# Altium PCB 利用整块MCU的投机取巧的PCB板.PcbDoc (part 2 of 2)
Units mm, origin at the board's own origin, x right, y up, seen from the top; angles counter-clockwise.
Board outline 162.08 x 191.08 mm, 2 copper layers (Top Layer, Bottom Layer); 156 components, 178 nets, 550 pads, 92 vias.
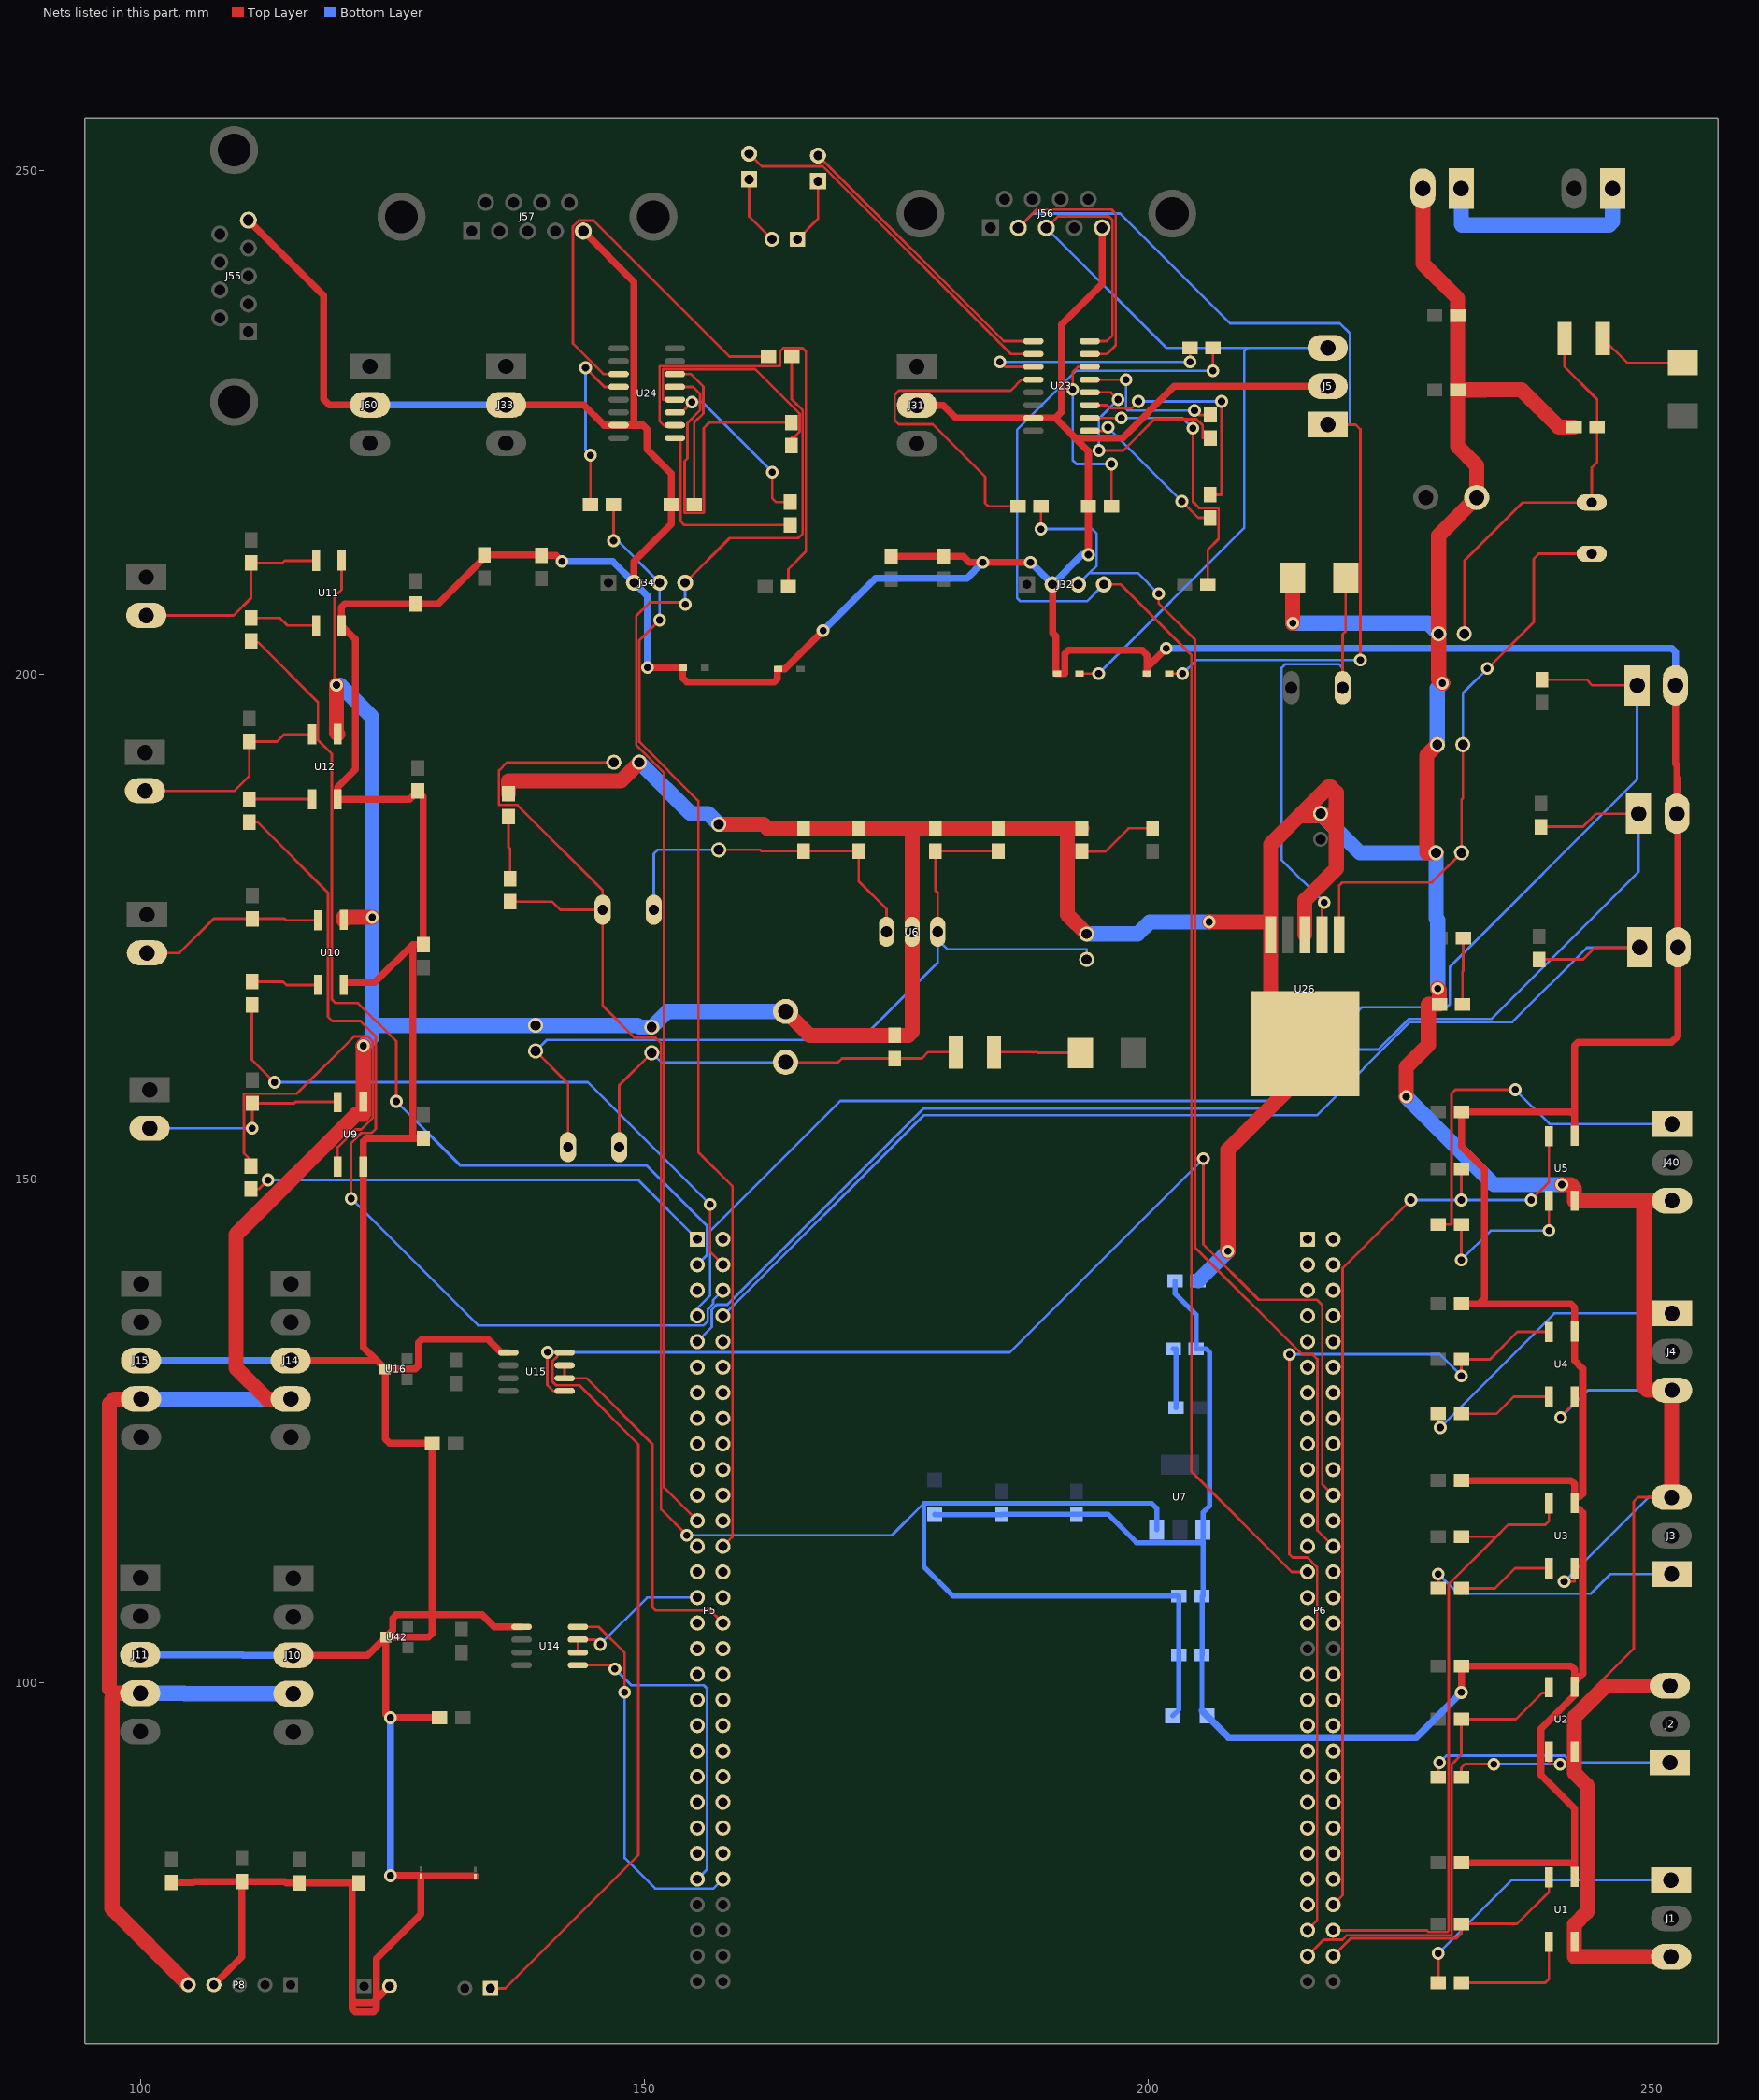
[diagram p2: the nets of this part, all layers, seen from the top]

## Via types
v1: diameter 1.27, hole 0.711, Top Layer to Bottom Layer, 92 vias

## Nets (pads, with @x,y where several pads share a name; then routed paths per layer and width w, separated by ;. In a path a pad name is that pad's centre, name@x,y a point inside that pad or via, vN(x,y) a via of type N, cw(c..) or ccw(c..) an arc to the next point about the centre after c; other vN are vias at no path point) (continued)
GND: C8.2 C12.2 C13.2 C17.2 C30.2 C33.2 C37.2 C45.2 C46.2 C48.2 C52.2 C73.2 C74.2 C75.2 C76.2 C77.2 C78.2 C80.2 C81.2 D9.1 J1.3 J2.3 J3.3 J4.3 J10.4 J11.4 J14.4 J15.4 J40.3 LED1.2 LED3.2 LED6.2 P2.2 P8.5 R24.1 U1.2 U2.2 U3.2 U4.2 U5.2 U6.2 U9.3 U10.3 U11.3 U12.3 U26.3 U26.5 | length 786.2
  Top Layer w0.254: U12.3@119.589,194.108 119.589,199.339 119.278,199.65 119.278,207.747 119.97,208.438 U11.3@119.97,211.335 ; v1(240.919,126.289) 240.919,126.371 242.31,127.762 U4.2@242.31,128.354 ; v1(241.275,110.001) 242.31,110.033 U3.2@242.31,111.336 ; U2.2@242.31,93.125 242.31,96.565 242.31,97.472 248.183,103.346 248.183,117.96 248.602,118.379 J3.3@251.938,118.379
  Top Layer w0.5: U26.3@215.556,160.494 U26.3@215.556,163.377
  Top Layer w1.5: J11.4@99.999,98.938 97.693,98.938 ; J15.4@100.065,128.135 97.426,128.135 96.926,127.635 96.926,99.377 97.366,98.938 97.693,98.938 ; P8.5@104.751,70.009 97.18,77.58 97.18,98.425 97.693,98.938 ; J14.4@114.924,128.135 112.568,128.135 109.495,131.208 109.495,144.445 121.437,156.388 122.104,156.388 122.129,156.413 U9.3@122.129,157.626 v1(122.129,163.17) ; v1(119.456,198.97) 119.456,194.241 U12.3@119.589,194.108 ; U10.3@120.173,175.66 120.173,175.899 120.203,175.929 v1(122.996,175.929) ; LED1.2@136.529,188.193 136.529,189.433 136.554,189.459 147.674,189.459 C52.2@149.524,191.308 ; C48.2@157.396,185.162 161.828,185.162 162.226,184.763 C46.2@165.82,184.763 C45.2@171.281,184.763 177.165,184.763 ; C12.2@164.034,166.584 166.411,164.207 C8.2@174.838,164.207 176.213,164.207 176.575,164.569 U6.2@176.575,174.484 176.575,184.174 177.165,184.763 ; LED6.2@193.415,184.756 192.405,184.756 ; C30.2@193.898,174.277 191.973,176.202 191.973,184.325 192.405,184.756 ; v1(206.07,175.463) U26.5@212.156,175.463 ; v1(207.92,142.802) 207.92,152.859 U26.3@215.556,160.494 ; U26.5@212.156,174.202 U26.5@212.156,175.463 ; v1(214.347,205.121) D9.1@214.347,209.645 ; U26.3@215.556,163.377 212.166,163.377 212.166,183.159 215.022,186.015 ; U26.3@215.556,174.202 215.556,177.622 ; C81.2@217.108,186.221 C81.2@217.314,186.015 ; v1(225.603,158.115) 225.603,161.061 227.813,163.271 227.813,167.267 227.838,167.292 LED3.2@228.903,167.292 228.903,168.681 v1(228.727,168.857) ; P2.2@227.259,248.236 227.259,240.796 230.717,237.338 C77.2@230.717,235.626 C75.2@230.717,228.26 ; C80.2@228.559,182.332 227.66,182.332 227.635,182.357 227.635,192.002 C76.2@228.693,193.06 ; v1(229.21,199.161) 228.827,199.544 C74.2@228.827,204.056 228.827,213.814 C78.2@232.599,217.586 232.599,220.766 230.717,222.648 C75.2@230.717,228.26 ; v1(241.046,149.403) 241.935,149.403 242.31,149.028 U5.2@242.31,147.803 ; C73.2@242.263,224.584 240.741,224.584 237.056,228.27 233.477,228.27 233.467,228.26 C75.2@230.717,228.26 ; U5.2@242.31,147.785 U5.2@242.31,147.803 ; J2.3@251.771,99.665 245.41,99.665 242.31,96.565 U2.2@242.31,93.125 242.31,91.014 243.535,89.789 243.535,77.222 242.31,75.997 U1.2@242.31,74.252 242.31,72.814 242.341,72.782 J1.3@251.881,72.782 ; J3.3@251.938,118.379 J4.3@251.938,129.002 ; J4.3@251.984,129.002 J4.3@251.938,129.002 ; J40.3@251.984,147.798 249.555,147.798 ; 177.165,184.763 C37.2@178.883,184.763 C33.2@185.124,184.763 190.671,184.763 190.678,184.756 192.405,184.756 ; U26.5@212.156,175.463 212.156,183.159 215.011,186.015 215.022,186.015 ; 215.022,186.015 217.856,188.849 218.123,188.849 218.669,188.303 218.669,185.469 ; 215.022,186.015 C81.2@217.314,186.015 ; 215.556,177.622 215.556,177.633 218.669,180.746 ; 215.556,177.622 218.669,180.735 218.669,180.746 ; C81.2@217.314,186.015 218.669,184.66 ; C81.2@217.314,186.015 218.123,186.015 218.669,185.469 ; 218.669,180.746 218.669,184.66 ; 218.669,184.66 218.669,185.469 ; U5.2@242.31,147.803 243.561,147.803 243.566,147.798 249.555,147.798 ; 249.555,147.798 249.174,147.417 249.174,129.383 249.555,129.002 J4.3@251.938,129.002
  Bottom Layer w0.254: v1(240.919,126.289) 243.632,129.002 J4.3@251.984,129.002 ; v1(241.275,110.001) 249.652,118.379 J3.3@251.938,118.379
  Bottom Layer w1.5: J11.4@99.999,98.938 104.369,98.938 104.418,98.888 J10.4@115.192,98.888 ; J15.4@100.065,128.135 J14.4@114.924,128.135 ; v1(119.456,198.97) 119.798,198.97 122.996,195.771 v1(122.996,175.929) 122.996,165.129 ; v1(122.129,163.17) 122.996,164.037 122.996,165.129 ; C52.2@149.524,191.308 154.612,186.22 156.337,186.22 C48.2@157.396,185.162 ; C12.2@164.034,166.584 152.304,166.584 C13.2@150.743,165.023 149.503,165.023 149.328,165.199 C17.2@139.218,165.199 123.066,165.199 122.996,165.129 ; C30.2@193.898,174.277 198.966,174.277 200.152,175.463 v1(206.07,175.463) ; R24.1@204.964,139.846 v1(207.92,142.802) ; v1(214.347,205.121) 227.762,205.121 C74.2@228.827,204.056 ; C81.2@217.108,186.221 220.997,182.332 C80.2@228.559,182.332 228.559,175.809 228.727,175.641 v1(228.727,168.857) ; v1(225.603,158.115) 234.315,149.403 v1(241.046,149.403) ; C76.2@228.693,193.06 228.693,198.645 v1(229.21,199.161)
GND-SYS: C1.2 C3.2 C7.2 C10.2 C11.2 C14.2 C19.1 C20.1 C21.1 C22.1 C24.1 C31.1 C32.2 C34.1 C35.1 C38.2 C43.2 C47.1 C49.2 C53.2 C55.2 C61.2 C65.2 C67.2 C69.2 C71.1 C72.1 C90.1 C91.1 D40.1 D41.1 D42.1 D43.1 J5.2 J10.3 J11.3 J12.2 J13.2 J14.3 J15.3 J16.2 J31.2 J32.2 J33.2 J34.2 J55.5 J56.5 J57.5 J60.2 LED2.2 P8.4 P9.2 R24.2 U1.3 U2.3 U3.3 U4.3 U5.3 U7.1 U9.2 U10.2 U11.2 U12.2 U14.5 U15.5 U16.3 U23.15 U24.15 U42.3 | length 985.6
  Top Layer w0.7: C14.2@103.072,80.149 105.258,80.149 105.361,80.252 C11.2@110.072,80.252 ; P8.4@107.291,70.009 110.072,72.79 C11.2@110.072,80.252 ; J55.5@110.728,245.101 118.186,237.642 118.186,227.33 118.727,226.789 J60.2@122.799,226.789 ; J14.3@114.924,131.945 123.469,131.945 ; J10.3@115.192,102.698 122.566,102.698 U42.3@124.369,104.501 ; U10.2@120.173,169.209 120.173,169.443 123.247,169.443 127.025,173.222 127.025,173.197 ; P9.2@124.733,69.866 123.444,68.577 ; v1(124.816,80.823) 127.852,80.823 C3.2@127.852,80.797 ; C31.1@128.08,153.997 127.051,153.997 ; C90.1@129.703,96.5 v1(124.816,96.5) 124.696,96.5 124.369,96.827 U42.3@124.369,104.501 ; C1.2@133.237,80.76 133.237,80.797 C3.2@127.852,80.797 ; J33.2@136.287,226.789 143.993,226.789 146.025,224.757 U24.15@147.463,224.757 148.646,224.757 ; U15.5@136.512,132.732 135.788,132.732 134.459,134.061 127.953,134.061 127.61,133.718 127.61,131.445 127.279,131.115 U16.3@124.299,131.115 ; U14.5@137.831,105.517 135.122,105.517 133.921,106.718 128.971,106.718 ; v1(141.834,211.252) 141.251,211.835 C61.2@139.803,211.835 139.803,211.88 C72.1@134.126,211.88 134.126,211.605 129.54,207.019 C35.1@127.336,207.019 120.297,207.019 119.97,206.692 U11.2@119.97,204.883 121.336,203.517 121.336,197.523 121.336,190.596 119.589,188.849 U12.2@119.589,187.656 126.733,187.656 C47.1@127.539,188.462 128.08,187.921 C34.1@128.08,173.222 127.051,173.222 127.025,173.197 ; J57.5@143.96,244.019 148.996,238.982 148.996,225.107 148.646,224.757 ; J34.2@148.985,209.134 148.985,211.252 152.668,214.935 C67.2@152.668,216.881 152.668,219.95 150.266,222.352 150.266,224.351 149.86,224.757 148.646,224.757 ; v1(150.317,200.699) D43.1@153.797,200.699 ; D43.1@153.807,200.699 D43.1@153.797,200.699 ; v1(167.742,204.368) 163.945,200.572 D42.1@163.299,200.572 163.195,200.572 163.195,199.581 162.877,199.263 154.242,199.263 153.797,199.707 D43.1@153.797,200.699 ; J31.2@177.054,226.745 179.655,226.745 180.925,225.475 U23.15@188.611,225.475 190.78,225.475 ; v1(188.327,211.15) v1(183.591,211.15) 182.267,211.15 181.661,211.757 C69.2@179.719,211.757 ; J32.2@190.514,208.963 190.514,204.151 190.856,203.81 190.856,200.108 D41.1@190.952,200.108 191.694,200.108 191.719,200.133 191.719,202.044 192.088,202.413 199.415,202.413 199.898,201.93 D40.1@199.898,200.108 ; v1(194.07,211.912) C65.2@194.07,216.71 194.07,222.185 190.78,225.475 ; J56.5@195.435,244.341 195.435,238.768 191.414,234.747 191.414,226.06 190.817,225.463 ; D40.1@199.875,200.108 D40.1@199.898,200.108 ; v1(201.803,202.616) 199.974,200.787 199.974,200.108 D40.1@199.898,200.108 ; J5.2@217.817,228.622 202.587,228.622 197.46,223.495 192.786,223.495 190.817,225.463 ; C19.1@231.078,82.117 241.935,82.117 242.31,81.742 ; v1(231.078,99.009) C20.1@231.078,101.634 241.959,101.634 242.31,101.282 U2.3@242.31,100.051 ; C21.1@231.078,120.049 241.959,120.049 242.31,119.697 U3.3@242.31,118.389 ; C22.1@231.078,137.575 232.812,137.575 ; U1.3@242.31,80.704 242.31,81.742 ; U5.3@242.31,154.237 242.31,156.267 ; J13.2@252.33,198.944 252.33,191.154 252.472,191.012 252.472,189.738 ; J16.2@252.472,186.209 252.472,189.738 ; C11.2@110.072,80.252 114.351,80.252 114.478,80.125 C10.2@115.787,80.125 115.787,80.112 C7.2@121.031,80.112 ; 121.031,68.58 C7.2@121.031,80.01 ; 121.031,68.58 121.031,67.627 121.349,67.31 123.126,67.31 123.444,67.627 123.444,68.577 ; 121.031,68.58 121.361,68.25 123.117,68.25 123.444,68.577 ; C7.2@121.031,80.01 121.655,80.01 C7.2@121.655,80.125 121.031,80.125 C7.2@121.031,80.112 ; C7.2@121.031,80.01 C7.2@121.031,80.112 ; 123.444,68.577 123.444,72.593 127.852,77.001 C3.2@127.852,80.791 C3.2@127.852,80.797 ; 123.469,131.945 U16.3@124.299,131.115 ; 123.469,131.945 122.149,133.265 122.149,148.107 122.129,148.127 U9.2@122.129,151.175 122.129,153.67 122.456,153.997 127.051,153.997 ; U16.3@124.299,131.115 124.299,124.142 124.708,123.733 C91.1@128.971,123.733 128.971,106.718 ; U42.3@124.369,104.501 128.588,104.501 128.971,104.884 128.971,106.718 ; U42.3@124.369,104.501 125.044,105.177 125.044,106.362 125.4,106.718 128.971,106.718 ; 127.025,173.197 127.025,154.022 127.051,153.997 ; C69.2@179.719,211.757 C71.1@174.512,211.757 174.512,211.76 179.719,211.76 C69.2@179.719,211.757 ; 190.78,225.475 190.806,225.475 190.817,225.463 ; 232.812,137.575 241.935,137.575 242.31,137.2 U4.3@242.31,134.806 242.31,131.953 243.129,131.134 243.129,118.745 242.773,118.389 U3.3@242.31,118.389 ; 232.812,137.575 233.35,138.112 233.35,150.915 231.078,153.187 C24.1@231.078,156.625 241.952,156.625 242.31,156.267 ; 242.31,81.742 242.31,87.484 238.963,90.83 238.963,95.402 242.31,98.749 U2.3@242.31,99.576 U2.3@242.31,100.051 ; U2.3@242.31,100.051 243.129,100.87 243.129,116.84 242.773,117.196 242.31,117.196 U3.3@242.31,117.788 U3.3@242.31,118.389 ; 242.31,156.267 242.31,163.195 242.627,163.512 251.938,163.512 252.573,164.147 J12.2@252.573,172.947 252.573,189.738 252.548,189.763 252.497,189.763 252.472,189.738
  Bottom Layer w0.5: C55.2@178.824,116.68 178.842,116.662 185.485,116.662 C53.2@185.485,116.688 ; C53.2@185.485,116.694 C53.2@185.485,116.688 ; R24.2@202.678,139.846 202.678,138.569 204.772,136.474 LED2.2@204.772,133.117 205.74,133.117 206.121,132.736 206.121,117.54 205.447,116.865 U7.1@205.447,115.176 205.447,113.894 ; C43.2@205.342,108.588 C43.2@205.359,108.588 ; C32.2@205.855,96.68 205.342,97.193 C38.2@205.342,102.746 205.359,102.746 C43.2@205.359,108.588 ; C53.2@185.485,116.688 192.895,116.688 C49.2@192.895,116.694 196.012,116.694 198.838,113.868 205.421,113.868 205.447,113.894 ; C43.2@205.359,108.588 205.461,108.588 205.461,113.908 205.447,113.894
  Bottom Layer w0.7: J11.3@99.999,102.748 110.18,102.748 110.23,102.698 J10.3@115.192,102.698 ; J15.3@100.065,131.945 100.787,131.945 100.795,131.953 114.19,131.953 114.198,131.945 J14.3@114.924,131.945 ; J60.2@122.799,226.789 J33.2@136.287,226.789 ; v1(124.816,80.823) v1(124.816,96.5) ; v1(141.834,211.252) 146.867,211.252 J34.2@148.985,209.134 150.317,207.802 v1(150.317,200.699) ; v1(167.742,204.368) 172.949,209.575 182.016,209.575 v1(183.591,211.15) ; v1(188.327,211.15) J32.2@190.514,208.963 193.464,211.912 v1(194.07,211.912) ; v1(201.803,202.616) 251.961,202.616 252.33,202.248 J13.2@252.33,198.944 ; C32.2@205.342,97.193 205.342,97.18 207.984,94.539 226.607,94.539 v1(231.078,99.009)
IN1: J1.1 R1.2 | length 29
  Top Layer w0.254: R1.2@228.792,70.197 v1(228.792,73.127)
  Bottom Layer w0.254: v1(228.792,73.127) 236.067,80.402 J1.1@251.881,80.402
IN1_1: P6.58 R7.1 U1.4 | length 26
  Top Layer w0.254: P6.58@218.359,72.869 220.106,74.616 230.586,74.616 231.078,75.108 R7.1@231.078,76.039 236.592,76.039 239.77,79.216 U1.4@239.77,80.679
IN2: J2.1 R2.2 | length 24.9
  Top Layer w0.254: R2.2@228.792,90.585 228.792,91.919 v1(228.917,92.045)
  Bottom Layer w0.254: v1(228.917,92.045) 229.604,92.731 241.322,92.731 242.008,92.045 J2.1@251.771,92.045
IN2_1: P6.57 R6.1 U2.4 | length 47.3
  Top Layer w0.254: P6.57@215.819,72.869 217.422,74.473 219.278,74.473 219.726,74.921 230.002,74.921 230.124,75.043 230.124,91.869 231.078,92.823 R6.1@231.078,96.363 236.494,96.363 239.09,98.958 239.77,98.958 U2.4@239.77,99.551
IN3: J3.1 R50.2 | length 26.2
  Top Layer w0.254: R50.2@228.792,109.338 v1(228.792,110.759)
  Bottom Layer w0.254: v1(228.792,110.759) 230.738,108.812 243.939,108.812 245.885,110.759 J3.1@251.938,110.759
IN3_1: P6.56 R5.1 U3.4 | length 63.7
  Top Layer w0.254: P6.56@218.359,75.409 227.664,75.409 227.847,75.226 229.697,75.226 229.819,75.348 229.819,109.753 234.526,114.461 ; R5.1@231.078,114.461 234.526,114.461 ; U3.4@239.77,117.763 239.77,116.021 239.395,115.646 235.712,115.646 234.526,114.461
IN4: J4.1 R40.2 | length 29.1
  Top Layer w0.254: R40.2@228.792,126.653 228.792,125.487 v1(228.981,125.298)
  Bottom Layer w0.254: v1(228.981,125.298) 240.304,136.622 J4.1@251.984,136.622
IN4_1: P6.55 R4.1 U4.4 | length 89
  Top Layer w0.254: v1(214.02,132.563) 214.02,112.712 214.338,112.395 215.811,112.395 216.764,111.442 216.764,76.354 P6.55@215.819,75.409 ; v1(231.078,130.429) R4.1@231.078,132.071 233.925,132.071 236.652,134.798 239.77,134.798 U4.4@239.77,134.781
  Bottom Layer w0.254: v1(214.02,132.563) 228.944,132.563 v1(231.078,130.429)
IN5: J40.1 R31.2 | length 37.7
  Top Layer w0.254: R31.2@228.792,145.449 230.073,145.449 230.099,145.474 230.099,158.433 230.492,158.826 v1(236.423,158.826)
  Bottom Layer w0.254: v1(236.423,158.826) 239.832,155.418 J40.1@251.984,155.418
IN5_1: P6.54 R3.1 U5.4 | length 95.2
  Top Layer w0.254: P6.54@218.359,77.949 219.304,78.894 219.304,141.122 v1(226.06,147.879) ; v1(231.078,147.879) R3.1@231.078,150.972 ; v1(237.998,147.879) 239.77,149.651 U5.4@239.77,154.212
  Bottom Layer w0.254: v1(226.06,147.879) v1(231.078,147.879) v1(237.998,147.879)
IN_24V: P2.1 P4.1 | length 22
  Bottom Layer w1.5: P2.1@231.069,248.236 231.069,244.686 231.124,244.631 245.745,244.631 246.079,244.965 P4.1@246.079,248.236
K1: J12.1 P5.8 R51.2 | length 116.6
  Top Layer w0.254: R51.2@238.799,171.744 243.154,171.744 244.358,172.947 J12.1@248.763,172.947
  Bottom Layer w0.254: P5.8@157.807,136.369 177.724,156.286 216.738,156.286 225.984,165.532 236.144,165.532 243.535,172.923 248.763,172.923 J12.1@248.763,172.947
K2: J13.1 P5.7 R52.2 | length 140.7
  Top Layer w0.254: R52.2@239.067,199.517 243.484,199.517 244.057,198.944 J13.1@248.52,198.944
  Bottom Layer w0.254: P5.7@155.267,136.369 155.267,137.124 156.54,138.397 156.54,144.805 169.443,157.709 211.887,157.709 221.183,167.005 229.629,167.005 229.946,167.322 229.946,171.037 248.52,189.611 J13.1@248.52,198.944
K3: J16.1 P5.9 R53.2 | length 129.7
  Top Layer w0.254: R53.2@238.976,184.913 243.154,184.913 244.45,186.209 J16.1@248.662,186.209
  Bottom Layer w0.254: P5.9@155.267,133.829 156.692,135.254 156.692,136.982 157.188,137.477 158.255,137.477 177.724,156.947 211.861,156.947 217.729,162.814 222.834,162.814 225.857,165.837 234.061,165.837 248.662,180.438 J16.1@248.662,186.209
L1: P5.1 R20.2 | length 47.1
  Top Layer w0.254: R20.2@110.971,148.965 111.779,148.965 v1(112.674,149.86)
  Bottom Layer w0.254: v1(112.674,149.86) 149.397,149.86 P5.1@155.267,143.989
L1_out: J6.2 R26.2 U9.4 | length 21.2
  Top Layer w0.254: v1(111.1,154.991) 111.123,155.014 R26.2@111.123,157.474 115.291,157.474 115.418,157.601 U9.4@119.589,157.601
  Bottom Layer w0.254: J6.2@100.92,154.993 111.098,154.993 v1(111.1,154.991)
L2: P5.4 R21.2 | length 63.4
  Top Layer w0.254: R21.2@111.08,167.253 111.08,161.792 v1(113.309,159.563) ; v1(156.54,147.422) 156.54,142.716 P5.4@157.807,141.449
  Bottom Layer w0.254: v1(113.309,159.563) 144.399,159.563 v1(156.54,147.422)
L2_out: J7.2 R27.2 U10.4 | length 18.4
  Top Layer w0.254: J7.2@100.666,172.392 103.896,172.392 107.29,175.785 R27.2@111.123,175.785 114.3,175.785 114.45,175.635 U10.4@117.633,175.635
L3: P5.3 R22.2 | length 93.6
  Top Layer w0.254: R22.2@111.004,203.336 111.004,203.2 111.709,203.2 117.627,197.282 117.627,193.523 118.999,192.151 118.999,167.792 119.38,167.411 121.615,167.411 125.4,163.627 v1(125.4,157.658)
  Bottom Layer w0.254: v1(125.4,157.658) 131.775,151.282 150.266,151.282 156.21,145.339 156.21,142.392 P5.3@155.267,141.449
L3_out: J8.2 R28.2 U11.4 | length 21.1
  Top Layer w0.254: J8.2@100.59,205.876 109.26,205.876 111.004,207.62 R28.2@111.004,211.083 114.097,211.083 114.323,211.309 U11.4@117.43,211.309
L4: P5.6 R25.2 | length 90.7
  Top Layer w0.254: R25.2@110.826,185.37 111.62,185.37 118.631,178.359 118.631,166.052 119.05,165.633 121.844,165.633 123.368,164.109 123.368,154.94 122.953,154.525 121.92,154.525 120.929,153.534 v1(120.929,148.006)
  Bottom Layer w0.254: v1(120.929,148.006) 133.502,135.433 155.892,135.433 156.312,135.852 156.312,137.033 156.845,137.566 156.845,137.947 P5.6@157.807,138.909
L4_out: J9.2 R29.2 U12.4 | length 20.9
  Top Layer w0.254: J9.2@100.463,188.477 109.337,188.477 110.826,189.967 R29.2@110.826,193.371 113.563,193.371 114.275,194.082 U12.4@117.049,194.082
MCU_RX: P3.1 S14.1 | length 6.6
  Top Layer w0.254: P3.1@165.213,243.208 167.244,245.239 S14.1@167.244,248.975
MCU_TX: P3.2 S15.1 | length 6.9
  Top Layer w0.254: S15.1@160.413,249.16 160.413,245.468 P3.2@162.673,243.208
NetC8_1: C8.1 C12.1 C13.1 F1.2 L1.1 | length 41.7
  Top Layer w0.254: L1.1@147.518,153.125 147.518,159.257 C13.1@150.743,162.483 ; C12.1@164.025,161.54 169.24,161.54 169.621,161.921 C8.1@174.838,161.921 177.546,161.921 178.185,162.56 F1.2@180.914,162.56
  Bottom Layer w0.254: C13.1@150.743,162.483 151.687,161.54 C12.1@164.025,161.54
NetC17_1: C17.1 C30.1 C33.1 C37.1 L1.2 U6.1 | length 88
  Top Layer w0.254: C17.1@139.218,162.659 142.438,159.438 L1.2@142.438,153.125 ; U6.1@179.12,174.488 179.12,178.359 178.883,178.596 C37.1@178.883,182.477 C33.1@185.124,182.477
  Bottom Layer w0.254: C17.1@139.218,162.659 140.313,163.754 171.45,163.754 179.12,171.424 U6.1@179.12,173.736 ; U6.1@179.12,174.488 U6.1@179.12,173.736 ; C30.1@193.898,171.737 193.898,172.72 193.873,172.745 180.11,172.745 U6.1@179.12,173.736
NetC45_1: C45.1 C46.1 C48.1 L4.1 U6.3 | length 35.3
  Top Layer w0.254: C48.1@157.396,182.622 161.519,182.622 161.663,182.477 C46.1@165.82,182.477 C45.1@171.281,182.477 171.281,179.513 174.035,176.759 U6.3@174.035,174.484
  Bottom Layer w0.254: L4.1@150.952,176.67 150.952,182.245 151.329,182.622 C48.1@157.396,182.622
NetC60_2: C60.2 U24.2 | length 47.4
  Top Layer w0.254: U24.2@153.051,224.757 151.917,224.757 151.536,225.138 151.536,230.599 151.562,230.624 163.441,230.624 163.474,230.657 163.474,232.093 163.792,232.41 165.722,232.41 166.04,232.093 166.04,212.217 164.304,210.482 C60.2@164.304,208.771
NetC62_1: C62.1 U24.5 | length 34.5
  Top Layer w0.254: U24.5@153.051,228.567 154.846,228.567 155.55,227.863 155.55,226.23 154.28,224.96 154.28,221.463 154,221.183 154,216.078 154.026,216.052 155.88,216.052 155.905,216.078 155.905,224.472 156.444,225.011 C62.1@164.608,225.011
NetC62_2: C62.2 U24.4 | length 23.2
  Top Layer w0.254: U24.4@153.051,227.297 151.867,227.297 151.841,227.322 151.841,230.294 151.867,230.32 161.011,230.32 165.42,225.91 165.42,224.104 164.836,223.52 164.633,223.52 164.608,223.495 C62.2@164.608,222.725
NetC63_1: C63.1 U23.1 | length 15.8
  Top Layer w0.254: U23.1@194.199,224.205 195.681,224.205 v1(196.012,224.536) ; v1(203.352,217.195) 204.981,215.567 C63.1@206.161,215.567
  Bottom Layer w0.254: v1(196.012,224.536) v1(203.352,217.195)
NetC63_2: C63.2 U23.3 | length 23.9
  Top Layer w0.254: U23.3@194.199,226.745 195.918,226.745 196.19,226.474 198.381,226.474 v1(199.034,227.127) ; C63.2@206.161,217.853 207.264,217.853 207.289,217.878 v1(207.289,227.127)
  Bottom Layer w0.254: v1(199.034,227.127) v1(207.289,227.127)
NetC64_2: C64.2 U23.2 | length 28.8
  Top Layer w0.254: U23.2@194.199,225.475 v1(197.333,225.475) ; v1(204.432,224.451) 204.432,217.17 205.067,216.535 206.959,216.535 206.985,216.51 206.985,213.462 205.907,212.384 C64.2@205.907,208.963
  Bottom Layer w0.254: v1(197.333,225.475) 203.408,225.475 v1(204.432,224.451)
NetC65_1: C65.1 U23.6 | length 18.8
  Top Layer w0.254: v1(192.507,228.295) 192.507,230.022 193.04,230.555 U23.6@194.199,230.555 ; C65.1@196.356,216.71 v1(196.356,220.904)
  Bottom Layer w0.254: v1(192.507,228.295) 192.507,221.297 192.9,220.904 v1(196.356,220.904)
NetC66_1: C66.1 U24.1 | length 19.9
  Top Layer w0.254: U24.1@153.051,223.487 153.619,223.487 153.619,215.217 153.987,214.849 C66.1@164.479,214.849
NetC66_2: C66.2 U24.3 | length 17.5
  Top Layer w0.254: U24.3@153.051,226.027 153.713,226.027 v1(154.737,227.051) ; v1(162.712,220.091) 162.712,217.487 163.065,217.135 C66.2@164.479,217.135
  Bottom Layer w0.254: v1(154.737,227.051) 155.753,227.051 v1(162.712,220.091)
NetC67_1: C67.1 U24.6 | length 15.4
  Top Layer w0.254: U24.6@153.051,229.837 154.623,229.837 155.87,228.59 155.87,225.925 154.954,225.01 C67.1@154.954,216.881
NetC70_1: C70.1 U23.5 | length 15.1
  Top Layer w0.254: U23.5@194.199,229.285 v1(197.815,229.285) ; v1(204.597,226.225) 205.045,225.777 C70.1@206.181,225.777
  Bottom Layer w0.254: v1(197.815,229.285) 197.815,226.377 197.968,226.225 v1(204.597,226.225)
NetC70_2: C70.2 U23.4 | length 22.7
  Top Layer w0.254: U23.4@194.199,228.015 196.292,228.015 v1(197.002,227.305) ; v1(195.123,222.25) 197.536,222.25 200.635,225.349 204.8,225.349 205.41,224.739 205.435,223.491 C70.2@206.181,223.491
  Bottom Layer w0.254: v1(195.123,222.25) 195.123,225.425 v1(197.002,227.305)
NetC73_1: C73.1 C74.1 F2.2 L5.1 | length 40.1
  Top Layer w0.254: C74.1@231.367,204.056 231.367,211.283 237.172,217.089 L5.1@244.014,217.089 244.014,220.548 244.549,221.083 C73.1@244.549,224.584 244.549,227.33 241.331,230.548 F2.2@241.331,233.351
NetC76_1: C76.1 C80.1 L5.2 U26.1 | length 56.5
  Top Layer w0.254: U26.1@218.956,174.202 218.956,179.07 219.273,179.387 228.155,179.387 C80.1@231.099,182.332 231.099,187.604 231.233,187.738 C76.1@231.233,193.06 ; v1(233.655,200.609) 238.252,205.207 238.252,211.501 238.76,212.009 L5.2@244.014,212.009
  Bottom Layer w0.254: C76.1@231.233,193.06 231.233,198.188 v1(233.655,200.609)
NetD2_2: D2.2 F1.1 | length 8.6
  Top Layer w0.254: F1.1@184.714,162.56 188.951,162.56 189.038,162.472 D2.2@193.276,162.472
NetD8_2: D8.2 F2.1 | length 8.9
  Top Layer w0.254: F2.1@245.131,233.351 247.524,230.957 D8.2@253.054,230.957
NetD9_2: D9.2 L6.2 U26.2 | length 47.7
  Top Layer w0.254: U26.2@217.255,174.202 217.255,177.174 v1(217.475,177.394) ; L6.2@219.294,198.714 219.294,204.013 219.607,204.325 D9.2@219.607,209.645
  Bottom Layer w0.254: v1(217.475,177.394) 213.233,181.635 213.233,200.66 213.614,201.041 218.913,201.041 219.294,200.66 L6.2@219.294,198.714
NetLED1_1: LED1.1 R30.1 | length 6.2
  Top Layer w0.254: LED1.1@136.529,185.907 136.529,182.904 136.68,182.753 R30.1@136.68,179.763
NetLED2_1: LED2.1 R32.1 | length 6.1
  Bottom Layer w0.5: LED2.1@202.486,133.117 202.754,133.117 R32.1@202.754,127.275
NetLED3_1: LED3.1 R73.1 | length 6.6
  Top Layer w0.254: LED3.1@231.189,167.292 231.189,170.536 231.266,170.613 R73.1@231.266,173.875
NetLED6_1: LED6.1 R90.1 | length 8
  Top Layer w0.254: LED6.1@193.415,182.47 195.783,182.47 198.062,184.749 R90.1@200.447,184.749
NetR1_1: R1.1 U1.1 | length 12.5
  Top Layer w0.254: R1.1@231.078,70.197 239.395,70.197 239.77,70.571 U1.1@239.77,74.252
NetR2_1: R2.1 U2.1 | length 13.2
  Top Layer w0.254: R2.1@231.078,90.585 231.078,91.517 231.457,91.897 v1(234.29,91.897) ; U2.1@239.77,93.125 239.77,91.948 v1(240.868,91.897)
  Bottom Layer w0.254: v1(234.29,91.897) v1(240.868,91.897)
NetR20_1: R20.1 U9.1 | length 37
  Top Layer w0.254: R20.1@110.971,151.251 110.971,151.818 110.287,152.502 110.287,158.394 110.312,158.42 115.519,158.42 121.209,164.109 122.555,164.109 123.063,163.601 123.063,156.026 121.905,154.868 121.326,154.868 119.589,153.131 U9.1@119.589,151.175
NetR21_1: R21.1 U10.1 | length 6.7
  Top Layer w0.254: R21.1@111.08,169.539 114.173,169.539 114.503,169.209 U10.1@117.633,169.209
NetR22_1: R22.1 U11.1 | length 6.7
  Top Layer w0.254: R22.1@111.004,205.622 113.843,205.622 114.582,204.883 U11.1@117.43,204.883
NetR25_1: R25.1 U12.1 | length 6.2
  Top Layer w0.254: R25.1@110.826,187.656 U12.1@117.049,187.656
NetR31_1: R31.1 U5.1 | length 16.4
  Top Layer w0.254: v1(231.078,141.924) R31.1@231.078,145.449 ; v1(239.77,144.831) U5.1@239.77,147.785
  Bottom Layer w0.254: v1(231.078,141.924) 233.985,144.831 v1(239.77,144.831)
NetR40_1: R40.1 U4.1 | length 9.4
  Top Layer w0.254: R40.1@231.078,126.653 234.569,126.653 236.271,128.354 U4.1@239.77,128.354
NetR50_1: R50.1 U3.1 | length 9.5
  Top Layer w0.254: R50.1@231.078,109.338 234.417,109.338 236.415,111.336 U3.1@239.77,111.336
PA0: P5.21
PA1: P5.24
PA4: P5.25
PA5: P5.28
PA6: P5.27
PA7: P5.30
PA8: P6.35
PA11: P6.32
PA12: P6.31
PA13: P6.30
PA14: P6.29
PA15: P6.28
PB0: P5.31
PB1: P5.34
PB2: P5.33
PB3: P6.9
PB4: P6.8
PB5: P6.7
PB6: P6.6
PB7: P6.5
PB8: P6.4
PB9: P6.3
PC0: P5.17
PC1: P5.20
PC2: P5.19
PC3: P5.22
PC6: P6.39
PC7: P6.38
PC8: P6.37
PC9: P6.36
PC12: P6.25
PC13: P5.5
PD0: P6.24
PD1: P6.23
PD3: P6.21
PD4: P6.20
PD5: P6.19
PD6: P6.18
PD7: P6.17
PD9: P6.53
PD10: P6.52
PD11: P6.51
PD12: P6.50
PD13: P6.49
PD14: P6.48
PD15: P6.47
PE0: P6.2
PE1: P6.1
PE2: P5.2
PE7: P5.41
PE8: P5.44
PE9: P5.43
PE10: P5.46
PE11: P5.45
PE12: P5.48
PE13: P5.47
PE14: P5.50
PE15: P5.49
PF2: P5.10
PF4: P5.12
PF5: P5.11
PF6: P5.14
PF7: P5.13
PF8: P5.16
PF9: P5.15
PF10: P5.18
PF11: P5.36
PF12: P5.35
PF13: P5.38
PF14: P5.37
PF15: P5.40
PG0: P5.39
PG1: P5.42
PG2: P6.46
PG3: P6.45
PG4: P6.44
PG5: P6.43
PG6: P6.42
PG7: P6.41
PG8: P6.40
PG9: P6.16
PG10: P6.15
PG11: P6.14
PG12: P6.13
PG13: P6.12
PG14: P6.11
PG15: P6.10
Rs232_Rxd1: D41.2 J5.3 J56.3 U23.8 | length 94.4
  Top Layer w0.254: J56.3@189.895,244.341 191.045,245.491 196.088,245.491 196.469,245.11 196.469,233.667 195.897,233.095 U23.8@194.199,233.095 ; D41.2@193.172,200.108 v1(195.087,200.108)
  Bottom Layer w0.254: J56.3@189.895,244.341 201.804,232.432 209.864,232.432 ; v1(195.087,200.108) 209.525,214.545 209.525,232.093 209.864,232.432 ; J5.3@217.817,232.432 209.864,232.432
Rs232_Txd1: D40.2 J5.1 J56.2 U23.7 | length 122.1
  Top Layer w0.254: J56.2@187.125,244.341 188.936,246.151 196.367,246.151 196.774,245.745 196.774,232.664 195.935,231.825 U23.7@194.199,231.825 ; D40.2@202.095,200.108 v1(203.429,200.108) ; J5.1@217.817,224.812 220.599,224.812 221.056,224.355 v1(221.056,201.447)
  Bottom Layer w0.254: J56.2@187.125,244.341 188.555,245.77 197.231,245.77 208.128,234.874 219.024,234.874 220.015,233.883 220.015,224.838 219.989,224.812 J5.1@217.817,224.812 ; v1(203.429,200.108) 204.768,201.447 v1(221.056,201.447)
U_R\E\2: P5.29 U14.2 U14.3 | length 15.2
  Top Layer w0.254: U14.2@143.419,102.977 U14.3@143.419,104.247 145.148,104.247 v1(145.625,103.771)
  Bottom Layer w0.254: v1(145.625,103.771) 150.283,108.429 P5.29@155.267,108.429
U_R\E\5: P5.32 U15.2 U15.3 | length 36.5
  Top Layer w0.254: U15.3@142.1,131.462 U15.2@142.1,130.192 144.268,130.192 150.812,123.647 150.812,107.455 151.13,107.137 156.559,107.137 P5.32@157.807,105.889
U_RX1-1: S14.2 U23.9 | length 29
  Top Layer w0.254: S14.2@167.244,251.515 185.664,233.095 U23.9@188.611,233.095
U_RX2: J34.3 P5.26 S8.1 | length 110.6
  Top Layer w0.254: v1(146.953,213.295) S8.1@146.953,216.881 ; v1(151.525,205.422) 149.504,203.402 149.504,193.345 155.372,187.477 155.372,152.629 158.75,149.25 158.75,114.452 P5.26@157.807,113.509
  Bottom Layer w0.254: v1(146.953,213.295) 147.364,213.295 J34.3@151.525,209.134 v1(151.525,205.422)
U_RX2_1: S8.2 U24.12 | length 17.9
  Top Layer w0.254: v1(144.17,230.454) 146.058,228.567 U24.12@147.463,228.567 ; S8.2@144.667,216.881 v1(144.667,221.778)
  Bottom Layer w0.254: v1(144.17,230.454) 144.17,222.275 v1(144.667,221.778)
U_RX3: P5.51 U14.1 | length 33
  Top Layer w0.254: U14.1@143.419,101.707 146.73,101.707 v1(147.091,101.346)
  Bottom Layer w0.254: v1(147.091,101.346) 148.717,99.72 155.892,99.72 156.21,99.403 156.21,81.432 P5.51@155.267,80.489
U_RX4: J32.3 P6.26 S5.1 | length 123.8
  Top Layer w0.254: v1(189.371,214.452) S5.1@189.371,216.71 ; v1(201.041,208.026) 201.041,207.091 204.668,203.464 204.668,143.159 215.265,132.563 216.306,132.563 216.789,132.08 216.789,115.079 P6.26@218.359,113.509
  Bottom Layer w0.254: v1(189.371,214.452) 194.437,214.452 194.894,213.995 194.894,210.803 194.175,210.083 ; J32.3@193.054,208.963 194.175,210.083 ; v1(201.041,208.026) 198.984,210.083 194.175,210.083
U_RX4_1: S5.2 U23.12 | length 34.2
  Top Layer w0.254: S5.2@187.085,216.71 184.15,216.71 183.832,217.027 183.832,219.647 178.638,224.841 175.26,224.841 174.854,225.247 174.854,227.787 175.26,228.194 186.361,228.194 187.452,229.285 U23.12@188.611,229.285
U_RX5: P6.22 U15.1 | length 120.4
  Top Layer w0.254: v1(140.386,132.766) 140.386,129.506 140.97,128.922 U15.1@142.1,128.922 ; v1(205.486,151.968) 205.486,143.459 210.972,137.973 216.764,137.973 217.272,137.465 217.272,119.676 P6.22@218.359,118.589
  Bottom Layer w0.254: v1(140.386,132.766) 186.284,132.766 v1(205.486,151.968)
U_TX1-1: S15.2 U23.10 | length 36.4
  Top Layer w0.254: S15.2@160.413,251.7 161.67,250.444 167.742,250.444 186.361,231.825 U23.10@188.611,231.825
U_TX2: J34.4 P5.23 S9.1 | length 131.6
  Top Layer w0.254: v1(154.065,206.985) 153.875,207.175 150.558,207.175 149.2,205.816 149.2,193.04 151.976,190.264 151.976,119.341 P5.23@155.267,116.049 ; J34.4@154.065,209.134 158.485,213.553 165.283,213.553 165.725,213.995 165.725,226.235 164.631,227.33 S9.1@164.631,231.572
  Bottom Layer w0.254: v1(154.065,206.985) J34.4@154.065,209.134
U_TX2_1: S9.2 U24.11 | length 42.7
  Top Layer w0.254: U24.11@147.463,229.837 145.943,229.837 142.926,232.855 142.926,244.475 143.51,245.059 144.983,245.059 158.47,231.572 S9.2@162.345,231.572
U_TX3: P5.52 U14.4 | length 37.5
  Top Layer w0.254: U14.4@143.419,105.517 145.486,105.517 148.057,102.946 v1(148.057,99.035)
  Bottom Layer w0.254: v1(148.057,99.035) 148.057,82.575 151.079,79.553 156.871,79.553 P5.52@157.807,80.489
U_TX4: J32.4 P6.27 S6.1 | length 158.5
  Top Layer w0.254: J32.4@195.594,208.963 197.264,208.963 204.292,201.935 204.292,120.929 214.252,110.969 P6.27@215.819,110.969 ; v1(206.44,230.149) S6.1@206.44,232.417
  Bottom Layer w0.254: J32.4@195.594,208.963 193.921,207.289 187.325,207.289 186.995,207.62 186.995,224.307 192.837,230.149 v1(206.44,230.149)
U_TX4_1: S6.2 U23.11 | length 23.8
  Top Layer w0.254: v1(185.293,231.038) 185.776,230.555 U23.11@188.611,230.555 ; v1(204.154,231.038) S6.2@204.154,232.417
  Bottom Layer w0.254: v1(185.293,231.038) v1(204.154,231.038)
U_TX5: P7.1 U15.4 | length 75.8
  Top Layer w0.254: P7.1@134.742,69.651 136.207,69.651 149.428,82.872 149.428,123.622 143.561,129.489 141.262,129.489 140.894,129.857 140.894,131.877 141.376,132.359 141.376,132.732 U15.4@142.1,132.732
VCC5V: C32.1 C38.1 C43.1 C52.1 L4.2 R30.2 U7.3 | length 227.8
  Top Layer w0.254: R30.2@136.68,177.477 140.868,177.477 141.676,176.67 L4.2@145.872,176.67 ; C52.1@146.984,191.308 136.394,191.308 135.585,190.5 135.585,187.096 135.611,187.071 137.414,187.071 145.872,178.613 L4.2@145.872,176.67 ; v1(154.229,114.605) 151.671,117.162 151.671,163.424 151.112,163.982 149.047,163.982 145.872,167.157 L4.2@145.872,176.67
  Bottom Layer w0.254: v1(154.229,114.605) 174.574,114.605 177.749,117.78 177.775,117.78 200.343,117.78 200.847,117.276 U7.3@200.847,115.176
  Bottom Layer w0.5: U7.3@200.847,115.176 200.847,117.276 200.343,117.78 177.775,117.78 177.749,117.754 177.749,111.481 180.642,108.588 C43.1@203.056,108.588 C38.1@203.056,102.746 203.056,97.31 C32.1@202.426,96.68
pads on no net: J55.1 J55.4 J55.6 J55.7 J55.8 J55.9 J55.10 J55.11 J56.1 J56.4 J56.6 J56.7 J56.8 J56.9 J56.10 J56.11 J57.1 J57.4 J57.6 J57.7 J57.8 J57.9 J57.10 J57.11 P5.53 P5.54 P5.55 P5.56 P5.57 P5.58 P5.59 P5.60 P6.59 P6.60 P7.2 U24.7 U24.8 U24.9 U24.10

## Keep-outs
Keep-Out Layer:
  lines w0.254: 247.446,255.114 94.606,255.114 94.606,64.292 256.428,64.292 256.428,255.093 ; 247.446,255.114 256.428,255.114 ; 246.591,255.684 246.591,255.684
